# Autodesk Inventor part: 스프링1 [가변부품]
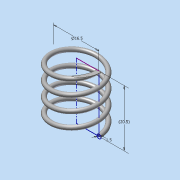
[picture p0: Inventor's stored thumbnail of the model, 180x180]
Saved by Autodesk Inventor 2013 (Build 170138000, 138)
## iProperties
Created: 2015-08
Part Number: 스프링1 [가변부품]
Material: 강철, 연강
Document SubType Name: Modeling
Designer: Administrator
Mass: 2.84502 g
Surface Area: 9.78731 cm^2
Volume: 0.361961 cm^3
Density: 7.86 g/cm^3
Author: Administrator
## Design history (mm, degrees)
sketch "스케치1"
  geometry: L1 (0, 0)-(8.25, 0); L2 (8.25, 0)-(8.25, 28); L3 (8.25, 28)-(0, 28); L4 (0, 28)-(0, 0); C1 r 0.75 at (8.25, 0)
  constraints: 8 end point, 2 parallel, 1 centre point, 1 coincident, 1 horizontal, 1 perpendicular
  dimensions: "d0" = 28 distance of L1.end L2.end (derived); "d2" = 16.5 diameter of L2 L4; "d3" = 1.5 diameter of C1
feature "코일1" sketch "스케치1" pitch "d4" = 10; turns "d6" = 4; dims "d5" = 28 (= d0), "d7" = 0, angle "d8" = 90 deg, angle "d9" = 90 deg, "d10" = 0, "d11" = 0
feature "분할1"
node "작업 평면1"
feature "분할2"
node "솔리드1"
other parameters: "d12" = 90 deg
